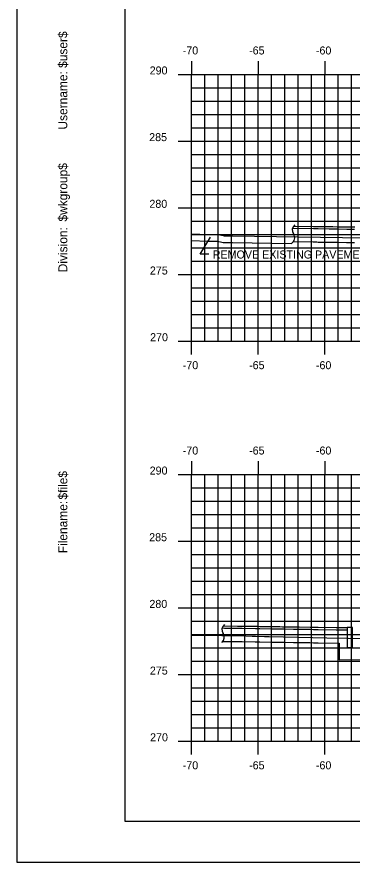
# Model space of a CAD drawing. Extents: x 853785 to 853955, y 366268 to 366378.
# Drawn here: x 853785.3 to 853810.5, y 366268.2 to 366331.6 of the extents above; entities that cross this region are included whole.
import ezdxf

# ---------------------------------------------------------------- set-up
doc = ezdxf.new("R2010")
doc.units = 0
for name, color, linetype in [('ANNOTATION', 7, 'Continuous'), ('BORDER', 7, 'Continuous'), ('D_Curb_Type1_Lt', 7, 'Continuous'), ('D_Roadway_Sidewalks_Paved', 7, 'Continuous'), ('D_Roadway_SubGrade', 7, 'Continuous'), ('D_Text_Standard', 7, 'Continuous'), ('H_V ANNOTATION', 7, 'Continuous'), ('MAJOR', 7, 'Continuous'), ('MINOR', 7, 'Continuous'), ('PLOT BOUNDARY', 7, 'Continuous'), ('S_Roadway_Centerline', 7, 'Continuous')]:
    doc.layers.add(name, color=color, linetype=linetype)

msp = doc.modelspace()

# ---------------------------------------------------------------- linework, layer by layer
at = {"layer": 'ANNOTATION'}
msp.add_lwpolyline([(853799.723, 366313.753), (853799.087, 366313.753), (853799.857, 366315.048)], dxfattribs=at)
at = {"layer": 'BORDER'}
for p, q in [((853793.435, 366376.236), (853793.435, 366271.236)), ((853793.435, 366271.236), (853953.435, 366271.236))]:
    msp.add_line(p, q, dxfattribs=at)
at = {"layer": 'D_Curb_Type1_Lt'}
msp.add_lwpolyline([(853810.098, 366285.777), (853810.098, 366284.277), (853810.515, 366284.277), (853810.515, 366285.777)], close=True, dxfattribs=at)
at = {"layer": 'D_Roadway_Sidewalks_Paved'}
for points in [[(853806.005, 366315.7), (853807.574, 366315.678), (853807.787, 366315.675), (853807.83, 366315.674), (853807.848, 366315.674), (853807.933, 366315.673), (853808.744, 366315.662), (853809.024, 366315.658), (853809.358, 366315.653), (853810.07, 366315.644), (853810.293, 366315.641), (853810.444, 366315.639), (853810.667, 366315.636)], [(853806.086, 366315.865), (853807.577, 366315.845), (853807.79, 366315.842), (853807.832, 366315.841), (853807.85, 366315.841), (853807.935, 366315.84), (853808.746, 366315.829), (853809.027, 366315.825), (853809.36, 366315.82), (853810.073, 366315.811), (853810.295, 366315.808), (853810.447, 366315.806), (853810.67, 366315.803)], [(853800.812, 366285.896), (853800.915, 366285.894), (853801.884, 366285.88), (853802.034, 366285.877), (853802.246, 366285.874), (853803.228, 366285.859), (853803.255, 366285.859), (853803.266, 366285.858), (853803.357, 366285.857), (853803.567, 366285.854), (853804.431, 366285.841), (853805.06, 366285.832), (853805.249, 366285.829), (853805.451, 366285.826), (853806.095, 366285.816), (853806.499, 366285.81), (853806.504, 366285.81), (853806.516, 366285.81), (853807.326, 366285.798), (853807.593, 366285.795), (853807.872, 366285.791), (853807.937, 366285.79), (853809.278, 366285.771), (853809.326, 366285.77), (853809.333, 366285.77), (853809.566, 366285.767), (853809.598, 366285.766), (853809.662, 366285.766), (853810.098, 366285.764)], [(853800.728, 366285.731), (853800.912, 366285.728), (853801.882, 366285.713), (853802.031, 366285.711), (853802.243, 366285.707), (853803.225, 366285.692), (853803.252, 366285.692), (853803.355, 366285.69), (853803.564, 366285.687), (853804.428, 366285.674), (853805.057, 366285.665), (853805.246, 366285.662), (853805.448, 366285.659), (853806.093, 366285.65), (853806.496, 366285.644), (853806.502, 366285.644), (853806.513, 366285.644), (853807.323, 366285.632), (853807.59, 366285.628), (853807.87, 366285.624), (853807.935, 366285.623), (853809.276, 366285.604), (853809.324, 366285.603), (853809.331, 366285.603), (853809.563, 366285.6), (853809.596, 366285.599), (853810.098, 366285.597)]]:
    msp.add_lwpolyline(points, dxfattribs=at)
at = {"layer": 'D_Roadway_SubGrade'}
msp.add_line((853809.515, 366284.6), (853809.515, 366283.332), dxfattribs=at)
for points in [[(853798.421, 366314.782), (853799.674, 366314.746), (853800.373, 366314.736), (853800.709, 366314.665), (853800.815, 366314.64), (853801.237, 366314.642), (853801.364, 366314.641), (853801.388, 366314.641), (853801.405, 366314.641), (853801.444, 366314.64), (853801.508, 366314.639), (853805.936, 366314.571)], [(853806.081, 366314.699), (853807.561, 366314.678), (853807.773, 366314.675), (853807.816, 366314.674), (853807.834, 366314.674), (853807.919, 366314.673), (853808.73, 366314.662), (853809.011, 366314.658), (853809.344, 366314.654), (853810.057, 366314.644), (853810.28, 366314.641), (853810.431, 366314.639), (853810.654, 366314.636)], [(853800.794, 366284.729), (853800.897, 366284.728), (853801.866, 366284.713), (853802.016, 366284.711), (853802.228, 366284.707), (853803.21, 366284.692), (853803.237, 366284.692), (853803.339, 366284.691), (853803.549, 366284.687), (853804.413, 366284.675), (853805.042, 366284.665), (853805.231, 366284.662), (853805.433, 366284.659), (853806.078, 366284.65), (853806.482, 366284.644), (853806.487, 366284.644), (853806.499, 366284.644), (853807.309, 366284.632), (853807.576, 366284.628), (853807.855, 366284.624), (853807.92, 366284.623), (853809.515, 366284.6)], [(853809.515, 366283.332), (853811.689, 366283.36)]]:
    msp.add_lwpolyline(points, dxfattribs=at)
for centre, start, end in [((853806.474, 366315.572), 126.60862, 216.60862), ((853805.693, 366314.992), 299.9613, 36.60862), ((853801.196, 366285.598), 125.98377, 215.98377), ((853800.41, 366285.027), 307.75603, 35.98377)]:
    msp.add_arc(centre, 0.486, start, end, dxfattribs=at)
at = {"layer": 'MAJOR'}
for p, q in [((853798.435, 366328.238), (853798.435, 366327.236)), ((853803.435, 366328.238), (853803.435, 366327.236)), ((853808.435, 366328.238), (853808.435, 366327.236)), ((853797.433, 366327.236), (853798.435, 366327.236)), ((853798.435, 366327.236), (853938.435, 366327.236)), ((853798.435, 366307.236), (853798.435, 366327.236)), ((853798.435, 366307.236), (853798.435, 366327.236)), ((853798.435, 366327.236), (853938.435, 366327.236)), ((853803.435, 366307.236), (853803.435, 366327.236)), ((853808.435, 366307.236), (853808.435, 366327.236)), ((853797.433, 366322.236), (853798.435, 366322.236)), ((853798.435, 366322.236), (853938.435, 366322.236)), ((853797.433, 366317.236), (853798.435, 366317.236)), ((853798.435, 366317.236), (853938.435, 366317.236)), ((853797.433, 366312.236), (853798.435, 366312.236)), ((853798.435, 366312.236), (853938.435, 366312.236)), ((853797.433, 366307.236), (853798.435, 366307.236)), ((853798.435, 366307.236), (853938.435, 366307.236)), ((853798.435, 366307.236), (853938.435, 366307.236)), ((853798.435, 366306.234), (853798.435, 366307.236)), ((853803.435, 366306.234), (853803.435, 366307.236)), ((853808.435, 366306.234), (853808.435, 366307.236)), ((853798.435, 366298.238), (853798.435, 366297.236)), ((853803.435, 366298.238), (853803.435, 366297.236)), ((853808.435, 366298.238), (853808.435, 366297.236)), ((853797.433, 366297.236), (853798.435, 366297.236)), ((853798.435, 366297.236), (853938.435, 366297.236)), ((853798.435, 366277.236), (853798.435, 366297.236)), ((853798.435, 366277.236), (853798.435, 366297.236)), ((853798.435, 366297.236), (853938.435, 366297.236)), ((853803.435, 366277.236), (853803.435, 366297.236)), ((853808.435, 366277.236), (853808.435, 366297.236)), ((853797.433, 366292.236), (853798.435, 366292.236)), ((853798.435, 366292.236), (853938.435, 366292.236)), ((853797.433, 366287.236), (853798.435, 366287.236)), ((853798.435, 366287.236), (853938.435, 366287.236)), ((853797.433, 366282.236), (853798.435, 366282.236)), ((853798.435, 366282.236), (853938.435, 366282.236)), ((853797.433, 366277.236), (853798.435, 366277.236)), ((853798.435, 366277.236), (853938.435, 366277.236)), ((853798.435, 366277.236), (853938.435, 366277.236)), ((853798.435, 366276.234), (853798.435, 366277.236)), ((853803.435, 366276.234), (853803.435, 366277.236)), ((853808.435, 366276.234), (853808.435, 366277.236))]:
    msp.add_line(p, q, dxfattribs=at)
at = {"layer": 'MINOR'}
for p, q in [((853799.435, 366307.236), (853799.435, 366327.236)), ((853800.435, 366307.236), (853800.435, 366327.236)), ((853801.435, 366307.236), (853801.435, 366327.236)), ((853802.435, 366307.236), (853802.435, 366327.236)), ((853804.435, 366307.236), (853804.435, 366327.236)), ((853805.435, 366307.236), (853805.435, 366327.236)), ((853806.435, 366307.236), (853806.435, 366327.236)), ((853807.435, 366307.236), (853807.435, 366327.236)), ((853809.435, 366307.236), (853809.435, 366327.236)), ((853810.435, 366307.236), (853810.435, 366327.236)), ((853798.435, 366326.236), (853938.435, 366326.236)), ((853798.435, 366326.236), (853799.437, 366326.236)), ((853798.435, 366325.236), (853938.435, 366325.236)), ((853798.435, 366325.236), (853799.437, 366325.236)), ((853798.435, 366324.236), (853938.435, 366324.236)), ((853798.435, 366324.236), (853799.437, 366324.236)), ((853798.435, 366323.236), (853938.435, 366323.236)), ((853798.435, 366323.236), (853799.437, 366323.236)), ((853798.435, 366321.236), (853938.435, 366321.236)), ((853798.435, 366321.236), (853799.437, 366321.236)), ((853798.435, 366320.236), (853938.435, 366320.236)), ((853798.435, 366320.236), (853799.437, 366320.236)), ((853798.435, 366319.236), (853938.435, 366319.236)), ((853798.435, 366319.236), (853799.437, 366319.236)), ((853798.435, 366318.236), (853938.435, 366318.236)), ((853798.435, 366318.236), (853799.437, 366318.236)), ((853798.435, 366316.236), (853938.435, 366316.236)), ((853798.435, 366316.236), (853799.437, 366316.236)), ((853798.435, 366315.236), (853938.435, 366315.236)), ((853798.435, 366315.236), (853799.437, 366315.236)), ((853798.435, 366314.236), (853938.435, 366314.236)), ((853798.435, 366314.236), (853799.437, 366314.236)), ((853798.435, 366313.236), (853938.435, 366313.236)), ((853798.435, 366313.236), (853799.437, 366313.236)), ((853798.435, 366311.236), (853938.435, 366311.236)), ((853798.435, 366311.236), (853799.437, 366311.236)), ((853798.435, 366310.236), (853938.435, 366310.236)), ((853798.435, 366310.236), (853799.437, 366310.236)), ((853798.435, 366309.236), (853938.435, 366309.236)), ((853798.435, 366309.236), (853799.437, 366309.236)), ((853798.435, 366308.236), (853938.435, 366308.236)), ((853798.435, 366308.236), (853799.437, 366308.236)), ((853798.435, 366277.236), (853798.435, 366297.236)), ((853799.435, 366277.236), (853799.435, 366297.236)), ((853800.435, 366277.236), (853800.435, 366297.236)), ((853801.435, 366277.236), (853801.435, 366297.236)), ((853802.435, 366277.236), (853802.435, 366297.236)), ((853804.435, 366277.236), (853804.435, 366297.236)), ((853805.435, 366277.236), (853805.435, 366297.236)), ((853806.435, 366277.236), (853806.435, 366297.236)), ((853807.435, 366277.236), (853807.435, 366297.236)), ((853809.435, 366277.236), (853809.435, 366297.236)), ((853810.435, 366277.236), (853810.435, 366297.236)), ((853798.435, 366296.236), (853938.435, 366296.236)), ((853798.435, 366296.236), (853799.437, 366296.236)), ((853798.435, 366295.236), (853938.435, 366295.236)), ((853798.435, 366295.236), (853799.437, 366295.236)), ((853798.435, 366294.236), (853938.435, 366294.236)), ((853798.435, 366294.236), (853799.437, 366294.236)), ((853798.435, 366293.236), (853938.435, 366293.236)), ((853798.435, 366293.236), (853799.437, 366293.236)), ((853798.435, 366291.236), (853938.435, 366291.236)), ((853798.435, 366291.236), (853799.437, 366291.236)), ((853798.435, 366290.236), (853938.435, 366290.236)), ((853798.435, 366290.236), (853799.437, 366290.236)), ((853798.435, 366289.236), (853938.435, 366289.236)), ((853798.435, 366289.236), (853799.437, 366289.236)), ((853798.435, 366288.236), (853938.435, 366288.236)), ((853798.435, 366288.236), (853799.437, 366288.236)), ((853798.435, 366286.236), (853938.435, 366286.236)), ((853798.435, 366286.236), (853799.437, 366286.236)), ((853798.435, 366285.236), (853938.435, 366285.236)), ((853798.435, 366285.236), (853799.437, 366285.236)), ((853798.435, 366284.236), (853938.435, 366284.236)), ((853798.435, 366284.236), (853799.437, 366284.236)), ((853798.435, 366283.236), (853938.435, 366283.236)), ((853798.435, 366283.236), (853799.437, 366283.236)), ((853798.435, 366281.236), (853938.435, 366281.236)), ((853798.435, 366281.236), (853799.437, 366281.236)), ((853798.435, 366280.236), (853938.435, 366280.236)), ((853798.435, 366280.236), (853799.437, 366280.236)), ((853798.435, 366279.236), (853938.435, 366279.236)), ((853798.435, 366279.236), (853799.437, 366279.236)), ((853798.435, 366278.236), (853938.435, 366278.236)), ((853798.435, 366278.236), (853799.437, 366278.236))]:
    msp.add_line(p, q, dxfattribs=at)
at = {"layer": 'PLOT BOUNDARY'}
msp.add_lwpolyline([(853785.342, 366268.177), (853955.342, 366268.177), (853955.342, 366378.177), (853785.342, 366378.177)], close=True, dxfattribs=at)
at = {"layer": 'S_Roadway_Centerline'}
for points in [[(853798.435, 366315.282), (853799.685, 366315.246), (853800.429, 366315.235), (853800.818, 366315.153), (853800.872, 366315.14), (853801.238, 366315.142), (853801.368, 366315.141), (853801.394, 366315.141), (853801.412, 366315.141), (853801.451, 366315.14), (853801.515, 366315.139), (853836.201, 366314.604), (853836.517, 366314.604), (853836.755, 366314.606), (853837.277, 366314.616), (853837.92, 366314.644), (853838.245, 366314.661), (853838.725, 366314.689), (853855.908, 366315.417)], [(853798.435, 366285.189), (853798.901, 366285.188), (853802.515, 366285.135), (853802.975, 366285.124), (853803.233, 366285.116), (853803.9, 366285.094), (853804.261, 366285.082), (853808.581, 366284.997), (853835.676, 366284.58), (853835.913, 366284.58), (853836.093, 366284.581), (853836.485, 366284.59), (853836.97, 366284.61), (853837.215, 366284.623), (853837.576, 366284.644), (853850.621, 366285.197)]]:
    msp.add_lwpolyline(points, dxfattribs=at)

# ---------------------------------------------------------------- texts
at = {"layer": 'BORDER'}
for s, p in [('$user$', (853789.12, 366327.728)), ('Username:', (853789.12, 366323.104)), ('$wkgroup$', (853789.12, 366316.206)), ('Division:', (853789.12, 366312.403)), ('$file$', (853789.12, 366295.362)), ('Filename:', (853789.12, 366291.335))]:
    msp.add_text(s, height=0.6696, rotation=90, dxfattribs=at).set_placement(p)
at = {"layer": 'D_Text_Standard'}
msp.add_text('REMOVE EXISTING PAVEMENT', height=0.6, dxfattribs=at).set_placement((853800.027, 366313.436))
at = {"layer": 'H_V ANNOTATION'}
for s, p in [('-70', (853797.777, 366328.736)), ('-65', (853802.753, 366328.736)), ('-60', (853807.761, 366328.736)), ('290', (853795.297, 366327.236)), ('285', (853795.26, 366322.236)), ('280', (853795.276, 366317.236)), ('275', (853795.313, 366312.236)), ('270', (853795.329, 366307.236)), ('-70', (853797.777, 366305.136)), ('-65', (853802.753, 366305.136)), ('-60', (853807.761, 366305.136)), ('-70', (853797.777, 366298.736)), ('-65', (853802.753, 366298.736)), ('-60', (853807.761, 366298.736)), ('290', (853795.297, 366297.236)), ('285', (853795.26, 366292.236)), ('280', (853795.276, 366287.236)), ('275', (853795.313, 366282.236)), ('270', (853795.329, 366277.236)), ('-70', (853797.777, 366275.136)), ('-65', (853802.753, 366275.136)), ('-60', (853807.761, 366275.136))]:
    msp.add_text(s, height=0.6, dxfattribs=at).set_placement(p)

doc.saveas('drawing.dxf')
